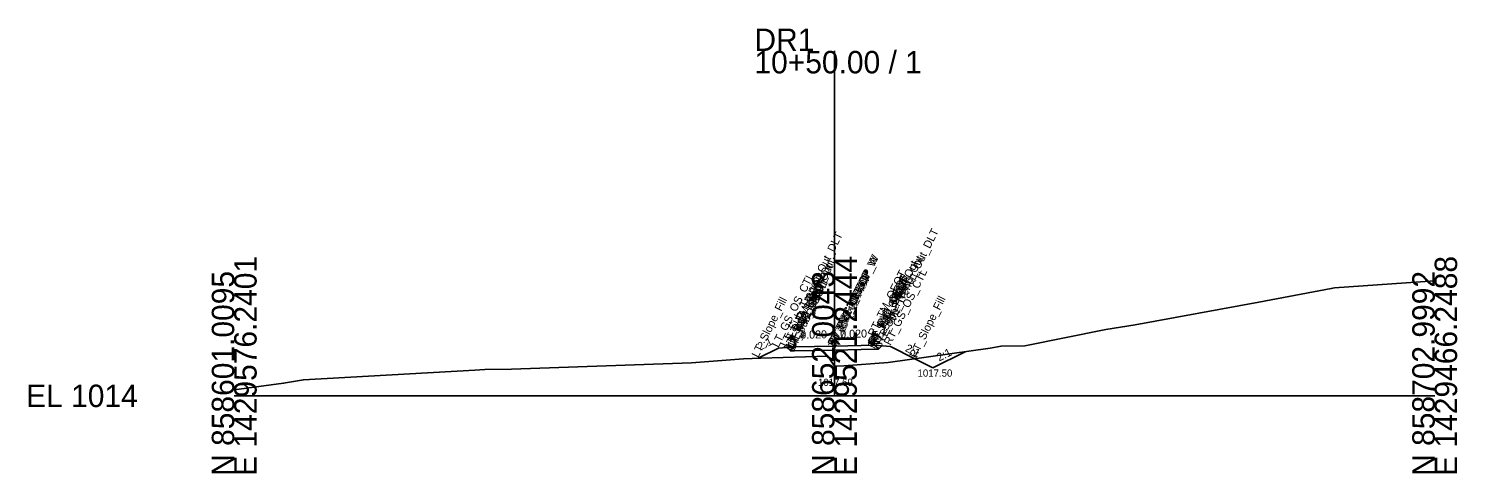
# Model space of a CAD drawing. Extents: x -26 to 1303, y -10 to 1029.
# Drawn here: x 1124.3 to 1302.8, y 490.3 to 545.9 of the extents above; entities that cross this region are included whole.
import ezdxf

# ---------------------------------------------------------------- set-up
doc = ezdxf.new("R2010")
doc.units = 0
for name, color, linetype in [('Default', 7, 'Continuous'), ('Exist Cross Section Cell', 7, 'Continuous'), ('Exist XS Center Line Elevation Label', 7, 'Continuous'), ('Exist XS Ground Line', 7, 'Continuous'), ('Prop CMT Pvmt Course 1', 7, 'Continuous'), ('Prop CMT Pvmt Course 2', 7, 'Continuous'), ('Prop CMT Pvmt Surface', 7, 'Continuous'), ('Prop CMT Pvmt Surface Overlay', 7, 'Continuous'), ('Prop CMT Shld Paved Course 1', 7, 'Continuous'), ('Prop CMT Shld Paved Course 2', 7, 'Continuous'), ('Prop CMT Slope Grass', 7, 'Continuous'), ('Prop CMT Subgrade Earthwork', 7, 'Continuous'), ('Prop XS Dump Level', 7, 'Continuous'), ('Prop XS EOT Tick Mark', 7, 'Continuous'), ('Prop XS SE Text', 7, 'Continuous'), ('Prop XS Side Slope Text', 7, 'Continuous')]:
    doc.layers.add(name, color=color, linetype=linetype)

msp = doc.modelspace()

# ---------------------------------------------------------------- linework, layer by layer
at = {"layer": 'Exist Cross Section Cell'}
for p, q in [((1225, 500), (1225, 543.1)), ((1150, 500), (1225, 500)), ((1225, 500), (1300, 500))]:
    msp.add_line(p, q, dxfattribs=at)
at = {"layer": 'Exist XS Ground Line'}
msp.add_lwpolyline([(1150, 500.74), (1156.17, 501.58), (1158.65, 502.02), (1180.05, 503.21), (1181.3, 503.28), (1184.66, 503.34), (1207.13, 504.11), (1213.62, 504.64), (1215.79, 504.7), (1224.19, 504.97), (1225, 503.69), (1226.16, 503.74), (1231.72, 504.16), (1244.44, 505.94), (1245.83, 506.22), (1248.8, 506.26), (1258.92, 508.3), (1262.57, 508.89), (1278.03, 511.72), (1287.07, 513.41), (1287.47, 513.49), (1300, 514.37)], dxfattribs=at)
at = {"layer": 'Prop CMT Pvmt Course 1'}
for points in [[(1225, 506.22), (1220, 506.12)], [(1225, 506.22), (1230, 506.32)]]:
    msp.add_lwpolyline(points, dxfattribs=at)
at = {"layer": 'Prop CMT Pvmt Course 2'}
for points in [[(1220, 505.62), (1225, 505.72)], [(1230, 505.82), (1225, 505.72)]]:
    msp.add_lwpolyline(points, dxfattribs=at)
at = {"layer": 'Prop CMT Pvmt Surface'}
for points in [[(1225, 506.22), (1220, 506.12)], [(1225, 506.22), (1230, 506.32)]]:
    msp.add_lwpolyline(points, dxfattribs=at)
at = {"layer": 'Prop CMT Pvmt Surface Overlay'}
for points in [[(1225, 506.22), (1220, 506.12)], [(1225, 506.22), (1230, 506.32)]]:
    msp.add_lwpolyline(points, dxfattribs=at)
at = {"layer": 'Prop CMT Shld Paved Course 1'}
for points in [[(1220, 506.12), (1219.74, 505.86)], [(1230, 506.32), (1230.25, 506.07)]]:
    msp.add_lwpolyline(points, dxfattribs=at)
at = {"layer": 'Prop CMT Shld Paved Course 2'}
for points in [[(1219.74, 505.86), (1219.49, 505.61)], [(1219.49, 505.61), (1220, 505.62)], [(1219.74, 505.86), (1219.74, 505.86)], [(1230.49, 505.83), (1230, 505.82)], [(1230.25, 506.07), (1230.25, 506.07)], [(1230.25, 506.07), (1230.49, 505.83)]]:
    msp.add_lwpolyline(points, dxfattribs=at)
at = {"layer": 'Prop CMT Slope Grass'}
for p, q in [((1230, 506.32), (1232, 506.16)), ((1235.06, 504.63), (1232, 506.16)), ((1237.31, 503.5), (1241.32, 505.5)), ((1237.31, 503.5), (1235.06, 504.63))]:
    msp.add_line(p, q, dxfattribs=at)
msp.add_lwpolyline([(1220, 506.12), (1218, 505.96), (1215.48, 504.7)], dxfattribs=at)
at = {"layer": 'Prop CMT Subgrade Earthwork'}
for points in [[(1225, 505.72), (1220, 505.62), (1219.49, 505.61), (1219.06, 506.04)], [(1225, 505.72), (1230, 505.82), (1230.49, 505.83), (1230.91, 506.24)]]:
    msp.add_lwpolyline(points, dxfattribs=at)
at = {"layer": 'Prop XS EOT Tick Mark'}
for points in [[(1220, 506.12), (1220, 507.12)], [(1230, 506.32), (1230, 507.32)]]:
    msp.add_lwpolyline(points, dxfattribs=at)

# ---------------------------------------------------------------- texts
at = {"layer": 'Default'}
for s, height, p in [('1017.50', 0.9, (1235.38, 502.4)), ('-', 0.0001, (1150, 500))]:
    msp.add_text(s, height=height, dxfattribs=at).set_placement(p)
at = {"layer": 'Exist Cross Section Cell'}
for s, p in [('DR1', (1215, 543.1)), ('10+50.00 / 1', (1215, 540.3)), ('EL 1014', (1124, 498.6))]:
    msp.add_text(s, height=2.8, dxfattribs=at).set_placement(p)
for s, p in [('E 1429576.2401', (1152.8, 490)), ('E 1429521.2444', (1227.8, 490)), ('E 1429466.2488', (1302.8, 490)), ('N 858601.0095', (1150, 490)), ('N 858652.0043', (1225, 490)), ('N 858702.9992', (1300, 490))]:
    msp.add_text(s, height=2.8, rotation=90, dxfattribs=at).set_placement(p)
at = {"layer": 'Exist XS Center Line Elevation Label'}
msp.add_text('1017.69', height=0.9, dxfattribs=at).set_placement((1222.94, 501.24))
at = {"layer": 'Prop XS Dump Level'}
for s, p in [('LT_Sub_Trench_Out_DLT', (1219.06, 506.04)), ('RT_Sub_Trench_Out_DLT', (1230.94, 506.28)), ('RT_PV1_OEEOP_W', (1225, 506.09)), ('LT_Sub_Trench_Out', (1219.49, 505.61)), ('LT_PS2_Shelf_Out', (1219.74, 505.86)), ('LT_PV1_OEEOP_W', (1225, 506.09)), ('RT_PS2_Shelf_Out', (1230.25, 506.07)), ('RT_Sub_Trench_Out', (1230.49, 505.83)), ('LT_GS_OS_CTL', (1218, 505.96)), ('LT_PS2_OEOP', (1219.74, 505.86)), ('LT_TM_OEOT', (1220, 507.12)), ('LT_PV1_OEOT', (1220, 506.12)), ('LT_PV2_OEOT', (1220, 505.87)), ('LT_Sub_OEOT', (1220, 505.62)), ('RT_PV2_OEEOP', (1225, 505.97)), ('LT_PV2_OEEOP', (1225, 505.97)), ('RT_Sub_OEEOP', (1225, 505.72)), ('LT_Sub_OEEOP', (1225, 505.72)), ('RT_TM_OEOT', (1230, 507.32)), ('RT_PV1_OEOT', (1230, 506.32)), ('RT_PV2_OEOT', (1230, 506.07)), ('RT_Sub_OEOT', (1230, 505.82)), ('RT_PS2_OEOP', (1230.25, 506.07)), ('RT_GS_OS_CTL', (1232, 506.24)), ('LT_Slope_Fill', (1215.48, 504.7)), ('PV1_PGL_W', (1225, 506.09)), ('RT_Slope_Fill', (1235.18, 504.64)), ('PV1_PGL', (1225, 506.22))]:
    msp.add_text(s, height=1, rotation=63.5833, dxfattribs=at).set_placement(p)
at = {"layer": 'Prop XS SE Text'}
for p in [(1220.73, 507.13), (1225.73, 507.23)]:
    msp.add_text('0.020', height=1, rotation=1.1458, dxfattribs=at).set_placement(p)
at = {"layer": 'Prop XS Side Slope Text'}
for rotation, p in [(26.5651, (1215.7, 505.64)), (333.4349, (1233.75, 505.63)), (26.5651, (1238.08, 504.29))]:
    msp.add_text('2:1', height=1, rotation=rotation, dxfattribs=at).set_placement(p)

doc.saveas('drawing.dxf')
